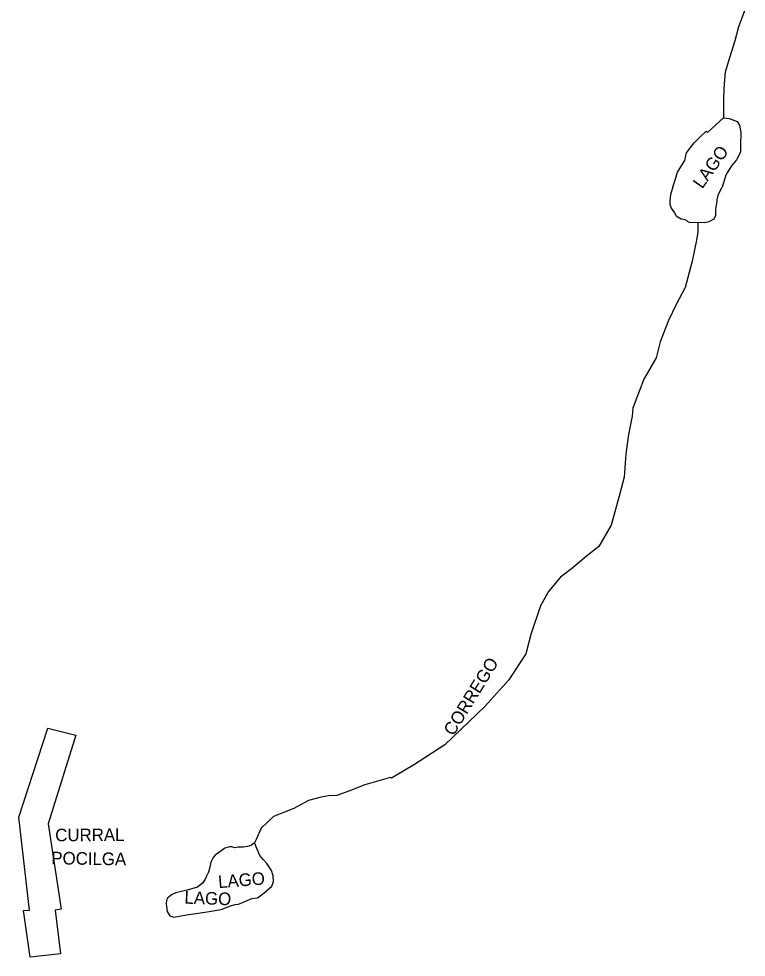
# Model space of a CAD drawing. Extents: x 325899 to 364828, y 7568995 to 7592502.
# Drawn here: x 343214.5 to 343445.5, y 7588257.3 to 7588555.4 of the extents above; entities that cross this region are included whole.
import ezdxf

# ---------------------------------------------------------------- set-up
doc = ezdxf.new("R2010")
doc.units = 0
for name, color, linetype in [('EDIFEXISTENT', 7, 'Continuous'), ('EDIFIDENTIF', 7, 'Continuous'), ('EDIFOBRAEXIS', 7, 'Continuous')]:
    doc.layers.add(name, color=color, linetype=linetype)

msp = doc.modelspace()

# ---------------------------------------------------------------- linework, layer by layer
at = {"layer": 'EDIFEXISTENT'}
for p, q in [((343214.47, 7588301.81), (343223.66, 7588330.12)), ((343223.66, 7588330.12), (343232.58, 7588327.86)), ((343232.58, 7588327.86), (343223.84, 7588299.65)), ((343217.92, 7588272.31), (343214.47, 7588301.81)), ((343223.84, 7588299.65), (343227.94, 7588272.62)), ((343216, 7588272.12), (343217.92, 7588272.31)), ((343218.05, 7588257.31), (343216, 7588272.12)), ((343227.94, 7588272.62), (343226.02, 7588272.22)), ((343226.02, 7588272.22), (343227.75, 7588258.34)), ((343227.75, 7588258.34), (343218.05, 7588257.31))]:
    msp.add_line(p, q, dxfattribs=at)
at = {"layer": 'EDIFOBRAEXIS'}
for points in [[(343445.53, 7588559.34), (343443.12, 7588552.82), (343441.9, 7588548.46), (343440.22, 7588543.04), (343438.8, 7588538.48), (343438.57, 7588534.75), (343438.27, 7588530.68), (343438.27, 7588523.93), (343440.15, 7588523.78), (343442.6, 7588522.84), (343443.38, 7588521.61), (343443.81, 7588519.31), (343443.66, 7588515.32), (343443.71, 7588513.04), (343442.47, 7588510.64), (343440.85, 7588508.74), (343439.5, 7588506.46), (343439.03, 7588505.75), (343437.87, 7588501.91)], [(343422.23, 7588501.91), (343423.23, 7588505.2), (343423.69, 7588506.75), (343426.06, 7588510.38), (343426.51, 7588512.8), (343429.01, 7588516.03), (343430.59, 7588517.65), (343432.79, 7588519.68), (343433.18, 7588519.28), (343438.27, 7588523.93)], [(343422.23, 7588501.91), (343421.43, 7588499.58), (343421.21, 7588497.62), (343421.31, 7588496.51), (343421.68, 7588495.29), (343422.77, 7588493.78), (343423.29, 7588492.82), (343424.82, 7588491.89), (343426.02, 7588491.63), (343426.79, 7588491.23), (343427.13, 7588490.9), (343427.92, 7588490.73), (343429.03, 7588490.77), (343432.39, 7588490.71), (343433.74, 7588491.08), (343435.33, 7588491.86), (343435.82, 7588493.07), (343435.86, 7588494.57), (343435.97, 7588495.81), (343436.24, 7588496.68), (343436.3, 7588497.88), (343436.74, 7588499.66), (343437.87, 7588501.91)], [(343430.19, 7588490.75), (343430.14, 7588487.76), (343429.71, 7588485.13), (343428.39, 7588478.43), (343426.13, 7588470.11), (343423.29, 7588464.63), (343420.88, 7588459.62), (343418.14, 7588452.77), (343416.88, 7588447.67), (343412.99, 7588440.98), (343410.23, 7588433.75), (343409.51, 7588431.71), (343409.29, 7588429.16), (343408.16, 7588423.4), (343407.32, 7588417.18), (343406.72, 7588409.78), (343405.19, 7588403.78), (343402.58, 7588394.52), (343398.74, 7588387.83), (343394.64, 7588384.58), (343390.08, 7588380.71), (343386.55, 7588378), (343382.71, 7588373.45), (343380.15, 7588368.89), (343377.07, 7588359.85), (343375.52, 7588353.7), (343370.07, 7588345.45), (343362.52, 7588336.96), (343349.84, 7588324.76), (343340.2, 7588318.56), (343332.85, 7588314.18), (343332.59, 7588314.45), (343328.08, 7588313.1), (343324.41, 7588312.09), (343319.32, 7588310.05), (343315.47, 7588308.73), (343312.8, 7588308.57), (343310.49, 7588308.21), (343306.46, 7588307.12), (343301.81, 7588304.58), (343295.4, 7588302.01), (343291.48, 7588298.3), (343289.92, 7588294.74), (343289.38, 7588293.65), (343288.26, 7588292.82), (343287.11, 7588292.47), (343285.83, 7588292.29), (343284.8, 7588292.27), (343284.19, 7588292.26), (343283.13, 7588292.08), (343282.11, 7588292.39), (343281.39, 7588292.38)], [(343281.39, 7588273.54), (343283.17, 7588274.01), (343284.21, 7588274.17), (343286.29, 7588274.99), (343288.54, 7588275.93), (343290.34, 7588276.23), (343292.41, 7588277.76), (343294.82, 7588279.9), (343295.37, 7588281.4), (343295.22, 7588283.16), (343294.77, 7588284.91), (343293.26, 7588287.1), (343292.1, 7588288.33), (343291.02, 7588289.64), (343289.38, 7588293.65)], [(343281.39, 7588292.38), (343279.96, 7588291.97), (343278.37, 7588290.82), (343276.85, 7588289.69), (343276.19, 7588288.99), (343275.51, 7588287.51), (343275.16, 7588285.94), (343274.74, 7588284.32), (343274.08, 7588283.02), (343273.69, 7588282.13), (343272.94, 7588280.95), (343271.27, 7588279.57), (343267.98, 7588278.66), (343264.34, 7588277.74), (343263, 7588277.15), (343262.19, 7588276.49), (343261.74, 7588276.07), (343261.4, 7588275.43), (343261.25, 7588274.24), (343261.56, 7588271.79), (343262.48, 7588270.44), (343263.67, 7588270.09), (343267.77, 7588270.8), (343270.66, 7588271.21), (343274.28, 7588271.78), (343278.73, 7588272.52), (343279.65, 7588272.83), (343281.39, 7588273.54)]]:
    msp.add_lwpolyline(points, dxfattribs=at)

# ---------------------------------------------------------------- texts
at = {"layer": 'EDIFIDENTIF'}
for s, rotation, p in [('LAGO', 54.6855, (343431.53, 7588501.18)), ('CORREGO', 58.4314, (343352.53, 7588327.37)), ('CURRAL', 0.2958, (343226.05, 7588294.12)), ('POCILGA', 359.2119, (343224.79, 7588286.83)), ('LAGO', 4.6235, (343277.95, 7588279.24)), ('LAGO', 357.8676, (343267.03, 7588274.34))]:
    msp.add_text(s, height=4, rotation=rotation, dxfattribs=at).set_placement(p)

doc.saveas('drawing.dxf')
